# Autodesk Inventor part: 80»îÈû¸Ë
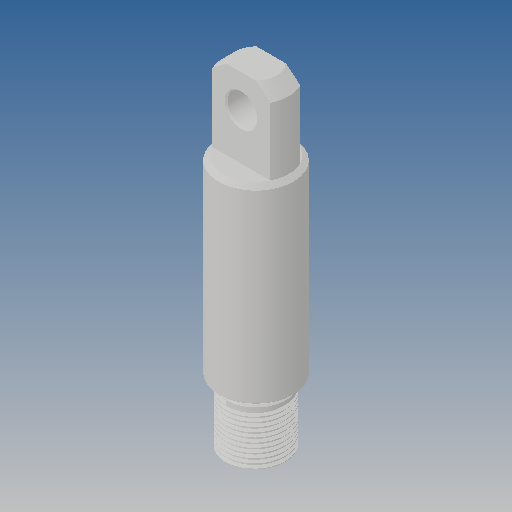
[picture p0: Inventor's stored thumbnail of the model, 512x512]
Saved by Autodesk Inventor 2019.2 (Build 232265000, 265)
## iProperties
Created: 2013-07
Part Number: 80»îÈû¸Ë
Material: Ogólny
Document SubType Name: Modeling
Designer: CADENGINEERING4
Density: 1 g/cm^3
Appearance: Domyślna
Author: CADENGINEERING4
Revision Number: ÈÎºÎ
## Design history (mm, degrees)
feature "µ¹½Ç1"
node "Bryła1"
